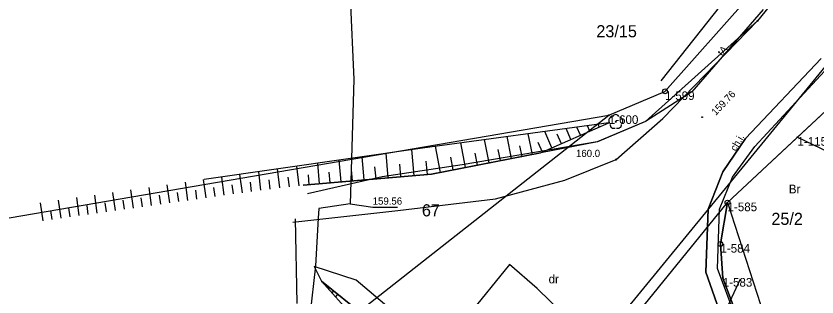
# Model space of a CAD drawing. Extents: x 5598798 to 5599616, y 5661498 to 5662453.
# Drawn here: x 5599039.1 to 5599122.4, y 5661605.1 to 5661634.4 of the extents above; entities that cross this region are included whole.
import ezdxf

# ---------------------------------------------------------------- set-up
doc = ezdxf.new("R2010")
doc.units = 0
for name, color, linetype in [('BUBZ_L_1', 7, 'Continuous'), ('Dzialki', 7, 'Continuous'), ('Kontury', 7, 'Continuous'), ('KTCR_E_T_1', 7, 'Continuous'), ('KTCR_L_1', 7, 'Continuous'), ('KTJZ_L_0', 7, 'Continuous'), ('KTKR_L_0', 7, 'Continuous'), ('KTOK_L_4', 7, 'Continuous'), ('Numery_dzialek', 7, 'Continuous'), ('Numery_punktow', 7, 'Continuous'), ('Numery_uzytkow', 7, 'Continuous'), ('OBOP_T_1', 7, 'Continuous'), ('Punkty', 7, 'Continuous'), ('RTPW_T_0', 7, 'Continuous'), ('RTPW_T_1', 7, 'Continuous'), ('SUOW_L_0', 7, 'Continuous'), ('SUPE_L_3', 7, 'Continuous'), ('SUPT_E_T_0', 7, 'Continuous'), ('SUPT_L_0', 7, 'Continuous'), ('SUPW_L_0', 7, 'Continuous'), ('SUTW_T_0', 7, 'Continuous'), ('Uzytki', 7, 'Continuous')]:
    doc.layers.add(name, color=color, linetype=linetype)

# ---------------------------------------------------------------- blocks, each defined once
blk = doc.blocks.new('GRO')
blk.add_circle((0, 0), 0.045)
blk = doc.blocks.new('GRT')
blk.add_circle((0, 0), 0.25)
blk = doc.blocks.new('POINT_DISPLAY')
blk.add_line((0, 0), (0, 0))
blk = doc.blocks.new('2_OBOP02_01')
blk.add_circle((0, 0), 0.045)
for centre, start, end in [((-0.356659, 0.115892), 102.144465, 221.860023), ((0, 0.375056), 30.140124, 149.859876), ((0.356659, 0.115892), 318.139977, 77.855535), ((-0.220404, -0.303384), 174.148182, 293.854228), ((0.220404, -0.303384), 246.145772, 5.851818)]:
    blk.add_arc(centre, 0.375, start, end)
blk = doc.blocks.new('2_RTPW02')
blk.add_circle((0, 0), 0.045)
blk = doc.blocks.new('2_RTPW01')
blk.add_circle((0, 0), 0.045)

msp = doc.modelspace()

# ---------------------------------------------------------------- linework, layer by layer
at = {"layer": 'BUBZ_L_1'}
for p, q in [((5599100.760838, 5661623.26659), (5599081.386943, 5661620.645806)), ((5599093.669555, 5661620.149117), (5599100.760838, 5661623.26659)), ((5599096.812485, 5661621.530813), (5599096.31386, 5661622.66503)), ((5599097.799573, 5661621.964758), (5599097.425605, 5661622.81542)), ((5599098.786662, 5661622.398702), (5599098.537349, 5661622.96581)), ((5599099.77375, 5661622.832646), (5599099.649094, 5661623.1162)), ((5599090.621003, 5661619.552358), (5599090.17427, 5661621.834503)), ((5599092.806125, 5661619.980099), (5599092.384592, 5661622.133502)), ((5599094.838308, 5661620.662925), (5599094.090372, 5661622.36425)), ((5599095.825397, 5661621.096869), (5599095.391453, 5661622.083958)), ((5599085.851036, 5661618.618629), (5599085.34929, 5661621.181809)), ((5599088.305244, 5661619.099044), (5599087.831802, 5661621.517628)), ((5599093.85122, 5661620.228981), (5599093.417276, 5661621.216069)), ((5599081.386943, 5661620.645806), (5599058.629251, 5661617.361533)), ((5599077.812865, 5661617.536341), (5599077.591888, 5661620.098123)), ((5599080.489189, 5661617.767198), (5599080.254974, 5661620.482446)), ((5599082.298988, 5661617.92331), (5599093.669555, 5661620.149117)), ((5599083.250103, 5661618.109492), (5599082.718359, 5661620.825912)), ((5599087.095952, 5661618.862324), (5599086.852258, 5661620.10724)), ((5599089.479931, 5661619.328991), (5599089.249984, 5661620.503678)), ((5599091.729423, 5661619.769333), (5599091.512448, 5661620.877753)), ((5599072.905464, 5661617.113032), (5599072.70876, 5661619.393415)), ((5599075.287807, 5661617.318531), (5599075.079319, 5661619.735522)), ((5599081.885701, 5661617.88766), (5599081.765239, 5661619.284172)), ((5599084.569446, 5661618.367756), (5599084.311183, 5661619.6871)), ((5599066.518269, 5661616.4865), (5599066.285977, 5661618.466512)), ((5599068.538413, 5661616.7235), (5599068.29983, 5661618.757141)), ((5599070.657772, 5661616.919148), (5599070.472186, 5661619.070644)), ((5599076.531974, 5661617.425852), (5599076.424653, 5661618.670019)), ((5599079.131565, 5661617.650091), (5599079.017815, 5661618.96879)), ((5599060.735071, 5661615.73112), (5599060.468255, 5661617.626929)), ((5599062.635873, 5661615.998638), (5599062.368121, 5661617.901107)), ((5599064.551397, 5661616.25575), (5599064.325231, 5661618.183547)), ((5599067.521593, 5661616.604208), (5599067.403884, 5661617.607532)), ((5599068.951628, 5661616.771978), (5599082.298988, 5661617.92331)), ((5599069.582024, 5661616.826355), (5599069.491891, 5661617.871261)), ((5599071.765273, 5661617.01468), (5599071.669741, 5661618.122182)), ((5599074.079311, 5661617.214287), (5599073.978056, 5661618.388134)), ((5599055.064118, 5661614.932992), (5599054.798562, 5661616.819855)), ((5599056.951904, 5661615.198679), (5599056.686175, 5661617.086773)), ((5599058.840922, 5661615.464538), (5599058.57502, 5661617.353864)), ((5599061.684639, 5661615.864762), (5599061.550997, 5661616.81433)), ((5599063.588778, 5661616.132749), (5599063.454666, 5661617.085653)), ((5599065.528263, 5661616.370354), (5599065.413658, 5661617.347219)), ((5599049.408145, 5661614.136973), (5599049.143108, 5661616.020146)), ((5599051.292239, 5661614.40214), (5599051.027029, 5661616.286542)), ((5599053.177564, 5661614.66748), (5599052.912181, 5661616.553111)), ((5599056.007857, 5661615.065814), (5599055.875036, 5661616.009553)), ((5599057.896259, 5661615.331587), (5599057.763351, 5661616.275942)), ((5599059.787166, 5661615.597712), (5599059.653992, 5661616.543956)), ((5599043.763231, 5661613.342511), (5599043.498712, 5661615.222001)), ((5599045.643641, 5661613.607159), (5599045.37895, 5661615.487876)), ((5599047.525279, 5661613.87198), (5599047.260415, 5661615.753924)), ((5599050.350038, 5661614.269535), (5599050.217477, 5661615.211429)), ((5599052.234748, 5661614.534788), (5599052.1021, 5661615.477296)), ((5599054.120687, 5661614.800214), (5599053.987952, 5661615.743338)), ((5599041.884046, 5661613.078035), (5599041.6197, 5661614.9563)), ((5599044.703282, 5661613.474813), (5599044.57098, 5661614.414865)), ((5599046.584307, 5661613.739547), (5599046.451918, 5661614.680213)), ((5599048.466558, 5661614.004455), (5599048.334083, 5661614.945734)), ((5599042.823485, 5661613.210251), (5599042.691269, 5661614.14969)), ((5599070.866619, 5661606.777722), (5599075.229063, 5661601.930102)), ((5599076.471074, 5661602.299748), (5599070.866619, 5661606.777722)), ((5599071.282272, 5661606.445614), (5599071.227348, 5661606.376874)), ((5599071.697925, 5661606.113506), (5599071.588077, 5661605.976025)), ((5599072.113578, 5661605.781398), (5599071.948807, 5661605.575177)), ((5599072.529232, 5661605.44929), (5599072.309536, 5661605.174328))]:
    msp.add_line(p, q, dxfattribs=at)
at = {"layer": 'Dzialki'}
for p, q in [((5599106.61, 5661626.54), (5599118.28, 5661639.65)), ((5599127.81, 5661628.71), (5599120.4, 5661621.78)), ((5599100.76, 5661624.05), (5599106.61, 5661626.54)), ((5599032.45, 5661612.39), (5599100.76, 5661624.05)), ((5599075.49, 5661604.18), (5599100.76, 5661624.05)), ((5599120.4, 5661621.78), (5599113.12, 5661614.97)), ((5599120.4, 5661621.78), (5599134.74, 5661614.87)), ((5599087.14, 5661583.01), (5599113.12, 5661614.97)), ((5599113.12, 5661614.97), (5599112.38, 5661610.66)), ((5599113.12, 5661614.97), (5599118.57, 5661598.2)), ((5599112.38, 5661610.66), (5599112.62, 5661607.12)), ((5599112.62, 5661607.12), (5599113.88, 5661603.82))]:
    msp.add_line(p, q, dxfattribs=at)
at = {"layer": 'Kontury'}
for p, q in [((5599106.61, 5661626.54), (5599118.28, 5661639.65)), ((5599113.12, 5661614.97), (5599127.81, 5661628.71)), ((5599100.76, 5661624.05), (5599106.61, 5661626.54)), ((5599032.45, 5661612.39), (5599100.76, 5661624.05)), ((5599112.38, 5661610.66), (5599113.12, 5661614.97)), ((5599112.62, 5661607.12), (5599112.38, 5661610.66)), ((5599113.88, 5661603.82), (5599112.62, 5661607.12))]:
    msp.add_line(p, q, dxfattribs=at)
at = {"layer": 'KTCR_L_1'}
for p, q in [((5599122.86, 5661629.96), (5599114.98, 5661621.62)), ((5599115.95, 5661620.81), (5599123.66, 5661629.14)), ((5599114.98, 5661621.62), (5599112.62, 5661618.17)), ((5599113.65, 5661617.61), (5599115.95, 5661620.81)), ((5599112.62, 5661618.17), (5599111.12, 5661614.28)), ((5599112.3, 5661614.28), (5599113.65, 5661617.61)), ((5599111.12, 5661614.28), (5599110.86, 5661607.74)), ((5599112.09, 5661608.11), (5599112.3, 5661614.28)), ((5599110.86, 5661607.74), (5599112.63, 5661602.7)), ((5599113.93, 5661603.13), (5599112.09, 5661608.11))]:
    msp.add_line(p, q, dxfattribs=at)
at = {"layer": 'KTJZ_L_0'}
for p, q in [((5599124.14, 5661643.58), (5599116.23, 5661633.87)), ((5599116.23, 5661633.87), (5599104.58, 5661623.42)), ((5599106.39, 5661623.71), (5599116.23, 5661633.87)), ((5599114.98, 5661621.62), (5599122.86, 5661629.96)), ((5599101.52, 5661619.44), (5599106.39, 5661623.71)), ((5599104.58, 5661623.42), (5599099.57, 5661621.3)), ((5599099.57, 5661621.3), (5599093.67, 5661620.15)), ((5599112.62, 5661618.17), (5599114.98, 5661621.62)), ((5599093.67, 5661620.15), (5599082.3, 5661617.92)), ((5599096.17, 5661617.31), (5599101.52, 5661619.44)), ((5599082.3, 5661617.92), (5599068.95, 5661616.77)), ((5599111.12, 5661614.28), (5599112.62, 5661618.17)), ((5599088.98, 5661615.37), (5599096.17, 5661617.31)), ((5599078.8, 5661614.14), (5599088.98, 5661615.37)), ((5599110.86, 5661607.74), (5599111.12, 5661614.28)), ((5599067.89, 5661612.93), (5599078.8, 5661614.14)), ((5599090.42, 5661608.51), (5599079.64, 5661595.29)), ((5599093.32, 5661606.04), (5599090.42, 5661608.51)), ((5599074.48, 5661606.91), (5599070.1, 5661608.3)), ((5599070.1, 5661608.3), (5599070.87, 5661606.78)), ((5599112.63, 5661602.7), (5599110.86, 5661607.74)), ((5599070.87, 5661606.78), (5599076.47, 5661602.3)), ((5599077.87, 5661604.01), (5599074.48, 5661606.91)), ((5599096.07, 5661603.33), (5599093.32, 5661606.04))]:
    msp.add_line(p, q, dxfattribs=at)
at = {"layer": 'KTKR_L_0'}
for p, q in [((5599122.86, 5661629.96), (5599114.98, 5661621.62)), ((5599114.98, 5661621.62), (5599112.62, 5661618.17)), ((5599112.62, 5661618.17), (5599111.12, 5661614.28)), ((5599111.12, 5661614.28), (5599110.86, 5661607.74)), ((5599110.86, 5661607.74), (5599112.63, 5661602.7))]:
    msp.add_line(p, q, dxfattribs=at)
at = {"layer": 'KTOK_L_4'}
msp.add_line((5599106.208386, 5661627.645012), (5599119.296241, 5661644.153167), dxfattribs=at)
at = {"layer": 'Numery_dzialek'}
msp.add_line((5599114.430511, 5661607.011873), (5599112.603219, 5661603.084648), dxfattribs=at)
at = {"layer": 'SUOW_L_0'}
msp.add_line((5599070.513116, 5661613.339568), (5599070.225874, 5661608.370705), dxfattribs=at)
msp.add_line((5599070.513116, 5661613.339568), (5599070.225874, 5661608.370705), dxfattribs=at)
at = {"layer": 'SUPE_L_3'}
msp.add_line((5599094.830509, 5661594.368063), (5599125.304463, 5661631.572851), dxfattribs=at)
at = {"layer": 'SUPT_L_0'}
for p, q in [((5599116.831229, 5661635.062005), (5599109.40253, 5661626.489212)), ((5599109.40253, 5661626.489212), (5599104.580049, 5661623.418214)), ((5599104.580049, 5661623.418214), (5599099.565757, 5661621.303308)), ((5599099.565757, 5661621.303308), (5599085.483727, 5661618.902275)), ((5599085.483727, 5661618.902275), (5599077.188456, 5661617.643238)), ((5599077.188456, 5661617.643238), (5599069.41498, 5661615.875815)), ((5599068.113234, 5661613.285024), (5599068.303936, 5661604.455202))]:
    msp.add_line(p, q, dxfattribs=at)
at = {"layer": 'SUPW_L_0'}
for p, q in [((5599073.016947, 5661653.715445), (5599074.236749, 5661627.780953)), ((5599074.236749, 5661627.780953), (5599073.840448, 5661614.845864)), ((5599070.579928, 5661614.361567), (5599070.513116, 5661613.339568)), ((5599073.840448, 5661614.845864), (5599070.579928, 5661614.361567)), ((5599070.513116, 5661613.339568), (5599070.225874, 5661608.370705)), ((5599070.513116, 5661613.339568), (5599070.225874, 5661608.370705)), ((5599070.225874, 5661608.370705), (5599069.272086, 5661599.714965)), ((5599070.225874, 5661608.370705), (5599069.272086, 5661599.714965))]:
    msp.add_line(p, q, dxfattribs=at)
at = {"layer": 'SUTW_T_0'}
for p, q in [((5599073.840448, 5661614.845864), (5599076.185524, 5661614.50173)), ((5599076.185524, 5661614.50173), (5599078.764077, 5661614.50173))]:
    msp.add_line(p, q, dxfattribs=at)
at = {"layer": 'Uzytki'}
for p, q in [((5599106.61, 5661626.54), (5599118.28, 5661639.65)), ((5599127.81, 5661628.71), (5599113.12, 5661614.97)), ((5599100.76, 5661624.05), (5599106.61, 5661626.54)), ((5599032.45, 5661612.39), (5599100.76, 5661624.05)), ((5599113.12, 5661614.97), (5599112.38, 5661610.66)), ((5599112.38, 5661610.66), (5599112.62, 5661607.12)), ((5599112.62, 5661607.12), (5599113.88, 5661603.82))]:
    msp.add_line(p, q, dxfattribs=at)

# ---------------------------------------------------------------- block references
at = {"layer": 'BUBZ_L_1'}
for p in [(5599100.760838, 5661623.26659), (5599070.866619, 5661606.777722)]:
    msp.add_blockref('POINT_DISPLAY', p, dxfattribs=at)
at = {"layer": 'OBOP_T_1'}
msp.add_blockref('2_OBOP02_01', (5599101.485336, 5661623.369153), dxfattribs=at)
at = {"layer": 'Punkty'}
for name, p in [('GRT', (5599106.61, 5661626.54)), ('GRO', (5599100.76, 5661624.05)), ('GRO', (5599120.4, 5661621.78)), ('GRT', (5599113.12, 5661614.97)), ('GRT', (5599112.38, 5661610.66)), ('GRO', (5599112.62, 5661607.12))]:
    msp.add_blockref(name, p, dxfattribs=at)
at = {"layer": 'RTPW_T_0', "rotation": -3.0000000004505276e-06}
for p in [(5599116.23, 5661633.87), (5599101.52, 5661619.44)]:
    msp.add_blockref('2_RTPW01', p, dxfattribs=at)
at = {"layer": 'RTPW_T_1'}
msp.add_blockref('2_RTPW02', (5599110.480926, 5661623.860407), dxfattribs=at)

# ---------------------------------------------------------------- texts
at = {"layer": 'KTCR_E_T_1'}
msp.add_text('ch.i.', height=0.75, rotation=59.600002, dxfattribs=at).set_placement((5599113.974217, 5661620.252969))
at = {"layer": 'Numery_dzialek'}
for s, p in [('23/15', (5599099.465618, 5661632.165312)), ('67', (5599081.309867, 5661613.533183)), ('25/2', (5599117.68252, 5661612.644096))]:
    msp.add_text(s, height=1.26, dxfattribs=at).set_placement(p)
at = {"layer": 'Numery_punktow'}
for s, p in [('1-599', (5599106.61, 5661625.64)), ('1-600', (5599100.76, 5661623.15)), ('1-1153', (5599120.4, 5661620.88)), ('1-585', (5599113.12, 5661614.07)), ('1-584', (5599112.38, 5661609.76)), ('1-583', (5599112.62, 5661606.22))]:
    msp.add_text(s, height=0.9, dxfattribs=at).set_placement(p)
at = {"layer": 'Numery_uzytkow'}
for s, p in [('Br', (5599119.499675, 5661615.929479)), ('dr', (5599094.495066, 5661606.56313))]:
    msp.add_text(s, height=0.9, dxfattribs=at).set_placement(p)
at = {"layer": 'RTPW_T_0'}
msp.add_text('160.0', height=0.75, dxfattribs=at).set_placement((5599097.346498, 5661619.712228))
at = {"layer": 'RTPW_T_1'}
msp.add_text('159.76', height=0.75, rotation=46.138164, dxfattribs=at).set_placement((5599111.893433, 5661623.977036))
at = {"layer": 'SUPT_E_T_0'}
msp.add_text('tA', height=0.75, rotation=49.089652, dxfattribs=at).set_placement((5599112.559637, 5661630.163449))
at = {"layer": 'SUTW_T_0'}
msp.add_text('159.56', height=0.75, dxfattribs=at).set_placement((5599076.185524, 5661614.75173))

doc.saveas('drawing.dxf')
